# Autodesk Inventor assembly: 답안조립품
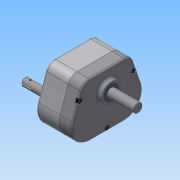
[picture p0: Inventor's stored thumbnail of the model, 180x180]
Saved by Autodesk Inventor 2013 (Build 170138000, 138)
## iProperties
Created: 2014-12
Part Number: 답안조립품
Document SubType Name: Assembly
Designer: Administrator
Author: Administrator
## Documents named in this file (14)
- C:\Users\Administrator\Desktop\441209V1032\441209V1032\답안조립품.iam
- C:\Users\Administrator\Desktop\441209V1032\441209V1032\본체.ipt
- C:\Users\Administrator\Desktop\441209V1032\441209V1032\M 5 x 35.ipt
- C:\Users\Administrator\Desktop\441209V1032\441209V1032\멈춤링.ipt
- C:\Users\Administrator\Desktop\441209V1032\441209V1032\메인기어.ipt
- C:\Users\Administrator\Desktop\441209V1032\441209V1032\메인축.ipt
- C:\Users\Administrator\Desktop\441209V1032\441209V1032\베어링- 6202.ipt
- C:\Users\Administrator\Desktop\441209V1032\441209V1032\베어링- 6203.ipt
- C:\Users\Administrator\Desktop\441209V1032\441209V1032\서브기어.ipt
- C:\Users\Administrator\Desktop\441209V1032\441209V1032\서브축.ipt
- C:\Users\Administrator\Desktop\441209V1032\441209V1032\오일시일-D-15.ipt
- C:\Users\Administrator\Desktop\441209V1032\441209V1032\오일시일-D-17.ipt
- C:\Users\Administrator\Desktop\441209V1032\441209V1032\커버.ipt
- C:\Users\Administrator\Desktop\441209V1032\441209V1032\키5x5.ipt
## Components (15 placed, 6 different names)
1. KS B 1003 - 미터 M 5 x 35:1
2. KS B 1336 17 x 1:1
3. KS B 2023 6202 - 15 x 35 x 11:1
4. KS B 2023 6203 - 17 x 40 x 12:1
5. KS B 2804 D D - 15 30 7:1
6. KS B 2804 D D - 17 30 8:1
7. KS B 1336 17 x 1:2
8. KS B 1336 17 x 1:3
9. KS B 2023 6202 - 15 x 35 x 11:2
10. KS B 2023 6203 - 17 x 40 x 12:2
11. KS B 2023 6203 - 17 x 40 x 12:3
12. KS B 2023 6203 - 17 x 40 x 12:4
13. KS B 2804 D D - 15 30 7:2
14. KS B 1003 - 미터 M 5 x 35:2
15. KS B 1003 - 미터 M 5 x 35:3
